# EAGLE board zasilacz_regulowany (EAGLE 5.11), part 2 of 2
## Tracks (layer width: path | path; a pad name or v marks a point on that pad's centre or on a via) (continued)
N$5 (continued)
  Top 0.406: 17.59,198.58 R34.2 | 17.59,198.58 17.77,198.51 IC6.7 | IC6.10 20.31,197.5 17.77,197.5 17.77,198.13 17.84,198.57 17.59,198.58
N$6  (via drill 0.6 pad 1.42)
  Top 0.406: 25.52,191.27 25.14,191.65 C23.1 25.18,192 24.54,192 24.12,192.42 | 24.12,192.42 IC6.13 | 24.12,192.42 v23.36,191.65
  Bottom 0.406: CA6V1.S 29.97,202.7 30.73,201.94 30.73,199.27 29.97,198.51 29.97,196.73 30.47,196.23 30.47,193.56 29.33,192.42 24.12,192.42 v23.36,191.65
N$7
  Top 0.406: R45.1 15.3,197.18 15.62,196.86 15.62,196.61 15.87,196.35 15.93,196.41 R41.2 16.06,196.41 16.5,196.86 16.5,196.73 19.04,196.73 IC6.9 19.04,192.54 19.93,191.65 20.02,191.74 C19.2
N$8  (via drill 0.6 pad 1.42)
  Top 0.406: R41.1 17.58,194.51 17.77,194.32 IC6.8 17.77,192.8 | 17.77,192.8 17.77,191.53 19.17,190.13 19.55,190.13 19.68,190 19.72,190.04 C19.1 | 17.77,192.8 v16.38,192.8 | CA6V1.E 27.43,206.01 27.36,206.07 R73.1
  Bottom 0.406: v16.38,192.8 19.93,196.35 19.93,200.8 21.33,202.2 22.35,202.2 22.98,202.83 22.98,205.37 23.24,205.62 27.17,205.62 CA6V1.E
N$9
  Top 0.406: LED10_V.K 66.92,61.5 68.7,63.28 77.21,63.28 78.1,62.39 78.1,58.58 79.24,57.44 81.91,57.44 82.04,57.57 R24.1
N$10  (via drill 0.6 pad 1.27)
  Top 0.406: Q3.3 36.27,185.77 36.19,185.69 35.94,185.94 v35.94,187.59 | 3.3,182.76 8.88,182.76 11.3,185.18 13.58,185.18 14.73,186.32 17.62,186.32 v18.18,186.88 | C18.1 32.89,190.38 34.21,189.07 D13.A
  Top 0.61: D13.A 34.28,188.1 33.45,187.26 D12.A 33.45,185.51 33.52,185.43 33.86,185.77 Q3.3 37.67,185.77 38.48,186.57 | 38.48,186.57 T5.3 | C1.1 39.87,185.18 38.48,186.57 | 3.3,182.76 1.65,184.42 1.65,196.48 3.8,198.64 3.8,233.21 4.11,233.51 Q2.B
  Bottom 0.406: v18.18,186.88 18.89,187.59 v35.94,187.59
N$11
  Bottom 0.406: TRAN2.1 53.39,182.94 53.08,182.64 R120.2
N$12  (via drill 0.6 pad 1.27)
  Top 0.305: IC5.32 50.42,200.41 v51.43,199.4
  Bottom 0.406: v51.43,199.4 51.43,193.05 53.46,193.05 56.64,189.88 56.64,188.61 57.02,188.23 57.02,186.32 56,185.3 56,183.27 55.98,183.37 TRAN2.2
N$13
  Bottom 0.305: TP1.PP 14.73,116.27 16.76,114.23 16.76,110.68 18.54,108.9 21.58,108.9 21.84,109.15 22.98,109.15 23.03,109.1 IC9.30
N$14
  Top 0.406: CA6V.E 29.08,193.81 29.71,193.18 30.6,193.18 31.05,192.73 R70.2
N$15
  Bottom 0.305: TP2.PP 16.38,115.89 17.39,114.87 17.39,111.06 18.92,109.54 21.33,109.54 21.71,109.92 23.11,109.92 23.24,109.79 23.35,109.9 IC9.31
N$16
  Top 0.406: IC6.14 25.39,194.19 26.66,192.92 26.66,191.78 26.79,191.65 C23.2 27.68,191.65 28.95,190.38 28.95,186.7 30.04,185.61 D12.C 30.04,185.51 29.59,185.05 29.59,178.7 30.98,177.3 R63.2
N$17
  Top 0.406: R66.1 26.1,209.63 CA6V1.A
N$18
  Bottom 0.305: TP3.PP 18.03,112.96 18.16,112.84 18.16,111.19 19.17,110.17 21.08,110.17 21.58,110.68 23.11,110.68 23.13,110.7 IC9.32
N$19
  Top 0.406: R32.2 15.62,204.61 13.33,206.87 13.33,210.7 9.52,214.51 9.52,223.91 10.15,224.55 10.15,224.42
  Top 0.61: 6.85,226.71 6.85,226.58 6.73,226.45
  Top 2.184: R29.1 6.85,226.71 7.36,226.71 9.65,224.42 10.15,224.42 14.09,224.42 18.41,228.74 24.78,228.74 25.75,229.7 25.75,232.95 Q4.E
N$20
  Top 0.406: LED9_I.K 79.37,60.62 80.39,59.6 82.16,59.6 | 82.16,59.6 82.1,59.66 R25.1 | 82.16,59.6 82.29,59.47
N$21
  Bottom 0.406: 38.98,77.02 39.11,76.9 J2.4 38.98,78.55 40,79.56 D11.C
N$22
  Top 0.406: R27.2 41.52,185.18 41.78,184.92 R14.1 41.72,183.33 42.41,182.64 D4.A
N$23
  Top 0.406: D1.C 36.65,178.65 38.78,180.78 D2.A
N$24
  Top 0.406: Q18.3 74.16,32.04 75.43,33.31 75.43,40.3 80.26,45.12 80.26,53.88 76.83,57.31 LED9_I.A
N$25
  Top 0.406: R33.2 39.55,189.05 39.43,188.92 T5.1 39.58,188.82 39.68,188.92 R27.1
N$26
  Bottom 0.305: TP4.PP 19.68,113.35 18.79,112.46 18.79,111.44 19.43,110.81 20.7,110.81 21.46,111.57 23.11,111.57 23.24,111.44 23.3,111.5 IC9.33
N$27
  Bottom 0.305: TP5.PP 21.33,116.27 23.24,114.36 24.63,114.36 25.14,113.85 25.14,113.35 25.18,113.3 IC9.34
N$28
  Bottom 1.27: Q4.B 14.83,232.9 14.17,233.56 Q2.E
N$29
  Bottom 0.305: TP6.PP 24.25,115.12 25.14,115.12 26.03,114.23 26.03,113.47 25.9,113.35 25.94,113.3 IC9.35
N$30
  Bottom 0.305: TP7.PP 24.63,116.52 26.79,114.36 26.79,113.47 26.8,113.46 IC9.36
N$31  (1 unrouted)
N$32
  Bottom 0.305: TP8.PP 26.16,116.27 27.55,114.87 27.55,113.6 27.6,113.55 IC9.37
N$33  (via drill 0.6 pad 1.42)
  Top 0.406: 23.74,180.86 23.79,180.9 Q8.3 22.35,180.99 21.84,181.49 21.84,181.62 | Q7.3 22.22,186.7 21.84,186.32 21.84,181.62 | v21.2,181.62 21.84,181.62
  Bottom 0.406: v21.2,181.62 20.95,181.62 20.52,181.19 20.52,179.87 C52.+
N$34
  Top 0.406: R37.2 47.81,176.99 48.76,177.94 49.52,177.94 49.52,178.45 | 49.52,178.45 49.52,178.57 49.55,178.55 TRAN1.4 49.55,178.67 49.52,178.7 | IC4.4 52.19,183.53 49.52,180.86 49.52,178.7 | 49.52,178.45 49.52,178.7
N$35
  Top 0.305: 54.55,210.32 52.32,210.32 52.06,210.58 49.78,210.58 49.65,210.45 49.65,209.43 IC5.10 | 54.55,210.32 J9.2 | R35.1 54.61,210.38 54.55,210.32
N$36
  Top 0.406: D2.C 35.38,180.91 35.3,180.99 35.37,181.05 Q3.1 35.37,183.34 35.11,183.08 R22.1
N$37  (2 unrouted)
  Top 0.406: R63.1 31.04,175.46 31.49,175.02 | J10.6 31.49,172.22
  Top 0.61: 31.49,172.22 31.49,175.02
N$38  (2 unrouted)
  Top 0.61: R64.1 33.4,172.99 J10.5
N$39  (via drill 0.6 pad 1.27)  (1 unrouted)
  Top 0.305: v40.25,203.72 41.14,203.72 41.78,203.08 43.3,203.08
  Top 0.406: R2.1 17.71,213.82 18.41,213.12 21.71,213.12 21.97,213.37 R3.2 22.03,211.91 v22.47,211.47 | 43.3,203.08 IC5.23
  Route2 0.254: 43.68,200.7 46.48,205.78
  Bottom 0.406: v22.47,211.47 25.01,214.01 33.65,214.01 35.94,211.72 35.94,207.4 39.62,203.72 v40.25,203.72
N$40
  Top 0.406: R2.2 15.87,215.91 13.84,217.94 D3.A | R39.2 20.06,205.75 19.49,206.33 R36.1 18.35,206.33 18.41,206.39 18.41,210.7 17.65,211.47 C46.+ | D5.A 6.47,190.64 7.91,192.07 C49.2
  Bottom 1.016: 6.6,211.59 C46.+
  Bottom 1.778: 6.6,195.08 6.6,211.59 6.6,214.51 10.03,217.94 D3.A
  Bottom 1.93: 6.6,195.08 R29.2 D5.A
N$41
  Top 2.54: 7.74,164.73 7.74,169.81
N$42  (via drill 0.6 pad 1.42)
  Top 0.406: v22.22,178.95 23.36,178.95 24.25,178.07 D14.C 24.81,178.37 25.01,178.57 26.54,178.57 26.79,178.32 D15.A
  Bottom 0.406: v22.22,178.95 22.24,178.95 20.59,177.3 C52.-
N$43
  Top 0.406: R18.1 34.73,212.93 35.55,213.75 L2.2
N$44
  Top 0.406: 49.55,185.56 TRAN1.1 | 49.55,185.56 49.55,185.79 49.4,185.94 | R53.2 44.83,187.34 45.59,186.57 48.51,186.57 49.52,185.56 49.55,185.56
N$45
  Top 0.406: IC4.1 56,182.51 56.64,181.88 59.94,181.88 60.95,180.86 60.95,178.95 60.93,178.93 TRAN3.2
N$46
  Top 0.61: J4.7 76.7,28.74 81.28,24.17 81.28,15.15 78.86,12.74 72.13,12.74 70.48,11.09 70.48,8.93 70.45,8.95 LED12_POWER.A
N$47  (1 unrouted)
N$48
  Top 2.54: 12.69,164.86 12.69,169.94
N$49
  Top 2.54: 17.52,164.86 17.52,169.94
N$50
  Top 2.54: 22.47,164.86 22.47,169.94
N$51
  Top 2.54: 53.84,219.34 58.92,219.34
N$52
  Top 2.54: 53.84,224.42 58.92,224.42
N$53
  Top 0.406: Q18.1 71.18,32.99 74.16,35.98 J4.6
N$54
  Top 0.406: R38.2 58.54,176.41 58.39,176.57 TRAN3.1
N$55
  Bottom 0.406: R121.2 53.44,177.05 TRAN2.4 53.44,177.91 53.46,177.94 53.46,179.34 53.55,179.42 T2.1
N$56
  Top 1.016: IC3.OUT 36.6,230.95 38.5,229.04 L1.2
  Bottom 0.406: C8.1 39.64,226.22 L1.2
N$57  (1 unrouted)
  Top 0.406: R5.2 54.16,197.56 53.84,197.12 53.84,195.08 55.11,193.81 LED1.A
  Bottom 0.406: LED1.A 56.89,193.05 57.14,192.8 60.07,192.8 60.7,192.16 60.7,187.59 60.32,187.21 60.32,184.42 57.65,181.75 51.68,181.75 50.92,180.99 46.73,180.99 45.72,179.97 45.72,169.94 29.08,169.94 J10.7
N$58
  Bottom 0.406: C47.1 19.79,107.61 20.19,108.01 21.97,108.01 22.22,108.27 23.24,108.27 23.27,108.3 IC9.29
N$59  (via drill 0.6 pad 1.27)
  Top 0.406: v7.74,219.72 5.84,217.82 5.84,198 4.31,196.48 4.31,187.97 5.58,186.7 8.88,186.7 9.77,187.59 R119.2 | v21.84,219.47 21.84,219.21 22.47,218.58 24.25,218.58 | 24.25,218.58 24.19,218.64 R74.2 | 24.25,218.58 24.38,218.45
  Bottom 0.254: D7.C 10.66,174.13 10.98,174.45
  Bottom 0.406: v7.74,219.72 8.88,220.86 21.2,220.86 21.84,220.23 v21.84,219.47
  Bottom 0.61: 10.03,175.27 10.03,175.02 9.77,175.27
  Bottom 0.813: 10.03,175.02 9.77,174.76 R119.2
  Bottom 2.54: D5.C 10.03,175.27 10.15,175.27 10.98,174.45 12.69,172.73 12.69,169.81 | 12.69,169.81 12.75,169.86 X2.4 | X2.3 12.75,164.65 12.69,164.6 12.69,169.81
N$60  (via drill 0.6 pad 1.27)
  Top 0.406: IC6.1 25.39,200.8 25.65,201.05 27.05,201.05 27.17,201.18 27.08,201.27 C42.1 26.83,201.27 26.54,201.56 v26.54,202.83 | R64.2 33.34,177.36 32,178.7 31.24,178.7 30.6,179.34 30.6,183.65 31.49,184.54 31.49,187.21 30.81,187.89 D13.C 30.81,188.27 29.84,189.24 29.84,191.02 28.7,192.16 28.7,192.29 27.55,193.43 27.55,195.34 v27.17,195.72
  Bottom 0.406: v27.17,195.72 27.17,202.07 v26.54,202.83
N$61  (via drill 3.2)  (1 unrouted)
  other vias: 61.59,165.11 2.79,165.11
N$62  (via drill 0.6 pad 2.18)
  other vias: 91.03,90.59
N$63
  Top 0.406: R28.1 10.79,69.25 11.81,70.27 11.81,77.28 BPT-14X.2
  Bottom 0.406: BPT-14X.2 10.15,90.46 11.42,91.73 T8.3
N$64
  Top 0.406: R72.2 49.78,189.88 49.91,189.75 50.03,189.75 50.29,190 LRED.A
N$65  (via drill 0.6 pad 1.42)
  Top 0.406: IC4.2 IC4.3 | IC4.2 54.73,184.8 | IC4.2 54.73,182.13 56,180.86 58.8,180.86 59.94,179.72 59.94,177.3 v60.57,176.67
  Bottom 0.406: v60.57,176.67 60.53,176.67 | R6.2 50.67,179.34 52.06,180.73 60.32,180.73 60.95,180.1 60.95,177.05 v60.57,176.67 | v60.57,176.67 60.57,176.8 60.15,177.22 T2.3
N$66
  Top 0.406: 50.67,187.84 LGREEN.A R71.2
N$67  (via drill 0.6 pad 1.27)
  Top 0.406: Q3.2 37.27,182.2 v37.08,182 | v17.52,189.62 16.25,189.62 v14.09,191.78
  Bottom 0.406: v37.08,182 37.08,188.73 36.44,189.37 29,189.37 28.24,188.61 26.72,188.61 25.95,189.37 17.77,189.37 v17.52,189.62 | v14.09,191.78 11.55,191.78 8.38,194.7 8.38,197.5 9.14,198.26 10.03,198.26 12.95,201.18 R10.1
N$68  (via drill 0.6 pad 1.27)
  Top 0.406: 53.89,224.32 X1.4 53.23,224.98 v47.49,224.98
  Bottom 0.406: C11.2 57.69,228.95 57.4,229.25 55.82,229.25 55.77,229.2 55.06,229.2 55.01,229.25 54.96,229.25 | C12.1 46.54,225.93 v47.49,224.98
  Bottom 2.184: X1.4 53.92,224.34 53.97,224.29 54.02,224.34 54.96,224.34 X1.3
  Bottom 2.54: 54.96,224.34 54.96,229.25 B1.~2
N$69
  Bottom 0.254: 57.18,219.76 57.65,219.85 X1.1
  Bottom 0.406: C6.1 57.18,219.76 56.76,219.34 | C5.1 46.56,230.22 46.98,230.64 48.79,230.64 48.91,230.52 49.02,230.52
  Bottom 2.184: X1.2 53.97,219.34 | X1.2 51.3,219.34 50.16,220.48 50.16,226.33 49.02,227.47 49.02,230.52 49.02,232.14 49.93,233.06 B1.~1 | X1.2 X1.1 60.19,219.34
N$70
  Top 0.406: LED11_OFF_ON.K 70.48,57.31 71.88,55.92 75.31,55.92 78.35,52.87 78.35,45.88 75.18,42.71 67.81,42.71 66.54,41.44 J4.3
N$71
  Top 0.406: LED11_OFF_ON.A 73.02,57.31 73.53,56.81 75.69,56.81 79.24,53.25 79.24,45.5 75.56,41.82 70.61,41.82 69.08,40.3 J4.4 69.08,37.63
N$72
  Top 0.406: Q15.3 91.1,35.98 90.8,35.98 90.8,40.55 90.42,40.93 90.42,54.27 92.32,56.17 LED10_V1.A
N$73
  Top 0.406: LED10_V1.K 94.86,62.39 95.75,63.28 107.82,63.28 108.83,62.27 108.83,59.35 109.28,58.9 | 109.34,58.84 109.28,58.9 | 109.28,58.9 R21.1
N$74
  Top 0.406: R23.1 108.96,56.55 107.06,58.46 LED9_I1.K
N$75
  Top 0.61: J3.7 102.23,31.28 100.96,30.01 92.45,30.01 88.13,25.69 88.13,15.15 91.69,11.59 97.4,11.59 98.42,10.58 LED12_POWER1.A
N$76
  Top 0.406: LED9_I1.A 104.52,59.47 100.71,55.66 96.01,55.66 93.09,52.74 93.09,43.72 96.26,40.55 99.94,40.55 100.96,39.53 100.96,33.69 99.94,32.68 Q16.3
N$77
  Top 0.406: LED11_OFF_ON1.K 98.42,58.2 97.4,57.19 95.12,57.19 91.31,53.38 91.31,41.44 92.2,40.55 92.2,37.76 92.09,37.65 J3.3
N$78
  Top 0.406: LED11_OFF_ON1.A 100.96,57.82 99.56,56.42 95.63,56.42 92.2,53 92.2,42.71 94.74,40.17 94.74,37.76 94.63,37.65 J3.4
N$79
  Top 0.305: 25.59,123.44 26.92,122.36 26.92,120.71 26.54,120.33 26.54,118.81 27.68,117.66
  Top 0.406: U$7.RS 29.71,119.7 28.06,118.04 28.06,117.92 27.74,117.6 R98.1 27.68,117.66 | 25.59,123.44 R103.1
N$80
  Bottom 0.406: IC9.7 40.85,106.7 42.54,108.39 Q5.2 43.03,108.88 C35.2
N$81
  Top 0.406: LED10_V2.A 6.47,58.84 10.15,55.15 17.27,55.15 19.81,52.61 19.81,47.03 16.25,43.47 13.2,43.47 10.03,40.3 10.03,32.93 11.42,31.53 12.57,31.53 12.61,31.49 | 12.69,31.41 12.61,31.49 | 12.61,31.49 Q13.3
N$82
  Top 0.406: LED10_V2.K 9.01,62.39 9.65,63.03 18.79,63.03 19.93,61.89 19.93,58.96 21.71,57.19 R19.1
N$83
  Top 0.406: LED9_I2.K 21.2,60.62 22.09,59.73 R20.1 25.01,59.73
N$84
  Top 0.61: J6.7 24,33.95 24.38,33.56 24.38,14.51 22.22,12.36 14.47,12.36 12.57,10.45 LED12_POWER2.A
N$85
  Bottom 0.406: IC9.8 41.09,105.9 41.65,105.34 Q5.1 43.3,103.57 42.54,102.8 42.54,99.88 43.05,99.5 42.91,99.36 C36.2
N$86
  Bottom 0.406: R116.2 30.16,88.27 29.71,87.82 LED7.A
N$87
  Bottom 0.406: R117.2 27.93,88.2 27.81,88.07 27.81,86.55 27.55,86.29 LED8.A
N$88  (via drill 0.6 pad 2.18)
  other vias: 96.16,90.59
N$89
  Bottom 0.406: U$11.A 73.66,69.53 73.78,69.66 R84.2
N$90
  Top 0.406: R100.1 32,117.66 32.76,118.43 U$7.CS 32.76,128.33 31.74,129.35 27.93,129.35 24.89,126.3 23.36,126.3 20.7,123.63 20.82,123.51 R105.1
N$91
  Top 0.406: R101.1 33.97,117.6 33.78,117.79 33.78,118.3 34.28,118.81 U$7.CLK 34.28,128.59 32.63,130.24 27.55,130.24 24.51,127.19 22.22,127.19 18.66,123.63 R106.1
N$92
  Bottom 0.406: R86.2 103.37,69.78 103.25,69.91 101.72,69.91 100.96,69.15 U$13.A
N$93  (via drill 0.6 pad 1.42)
  Top 0.406: U$7.LED+ 41.91,122.24 42.41,121.73 42.41,119.95 v42.03,119.44
  Bottom 0.406: R109.2 48.45,120.65 48.51,120.58 47.37,119.44 v42.03,119.44
N$94
  Bottom 0.305: R90.1 37.84,127.51 37.84,130.87 44.7,130.87 45.97,129.6 45.97,127.95 46.48,127.44 U$8.7
  Bottom 0.406: R91.2 39.49,124.46 R90.1
N$95  (via drill 0.7 pad 1.42)
  Top 0.61: v56.26,121.85 55.88,121.35 55.88,82.36 55.37,81.85 55.37,77.4 56.26,76.52 L3.2
  Top 0.813: IC7.3 66.42,77.15 65.78,76.52 L3.2
  Bottom 0.61: C32.1 55.88,121.86 v56.26,121.85
N$96
  Bottom 0.406: LED6.A 59.05,89.47
  Bottom 0.61: 59.05,89.47 R81.2
N$97
  Top 0.406: 100.2,94.78 100.2,94.68 100.32,94.55 | B2.AC2 91.05,90.87 90.68,91.24 C30.2 | C29.2 105.28,84.9 108.45,88.07 108.45,93.91 107.56,94.8 105.53,94.8 105.51,94.78 U$6.1
  Top 0.813: B2.AC2 91.05,90.74 95.09,94.78 100.2,94.78 U$6.1 105.38,94.78 105.41,94.8
  Bottom 0.406: U$6.1 105.38,94.78
N$98  (via drill 0.6 pad 2.18)
  other vias: 91.08,85.53
N$99  (via drill 0.6 pad 2.18)
  other vias: 96.11,85.51
N$100  (1 unrouted)
  Top 0.305: R92.2 40.13,175.27 39.87,175.02
  Top 0.406: D4.C 42.49,179.03 | 39.87,175.02 39.24,174.38 J10.3 | 41.91,178.57 41.91,177.81 40.51,176.41 40.51,175.53 40.25,175.27 R92.2
  Top 0.61: D4.C 42.36,179.03 41.91,178.57
N$101
  Top 0.406: Q14.3 20.91,32.25 22.73,34.07 22.73,40.3 22.35,40.68 22.35,54.14 18.66,57.82 18.66,60.74 18.79,60.87 LED9_I2.A
N$102  (via drill 3.2)
  other vias: 114.09,200.65
N$103
  Top 0.406: J6.3 13.84,41.82 14.47,42.45 16.5,42.45 20.7,46.65 20.7,53 17.77,55.92 14.09,55.92 12.57,57.44 LED11_OFF_ON2.K
N$104
  Bottom 0.406: R87.2 U$14.A
N$105
  Bottom 0.406: Q6.3 53.08,113.47 53.21,113.6 D8.A 53.21,116.27 55.62,118.68 L4.2
N$106
  Bottom 0.406: D10.C 49.64,114.6 D9.A
N$107
  Bottom 0.406: D8.K 53.21,121.09 53.02,120.33 R109.1 50.35,120.65 50.41,120.58 50.41,119.19 49.25,118.03 D9.C
N$108
  Bottom 0.406: L4.1 57.4,105.98 56.64,105.22 R108.2
N$109
  Top 0.406: 96.01,85.66 B2.AC1 94.1,83.5 C26.1 | 96.13,86.88 96.06,86.88 95.6,87.34 90.37,87.34 88.84,85.81 C27.1
  Top 0.813: B2.AC1 96.13,86.88 96.13,87.06 98.85,89.77 105.23,89.77 105.28,89.72 U$6.2
N$110
  Top 0.406: C29.1 99.43,85.02 99.18,84.77 98.93,84.77 94.23,80.07 C26.2
  Top 0.61: C26.2 90.8,80.2 90.61,80.39
  Top 0.813: IC7.1 74.29,77.28 79.37,72.2 C33.+ 83.56,72.2 83.94,72.58 83.94,78.42 84.96,79.44 89.66,79.44 90.61,80.39 91.18,80.96 91.18,85.41 B2.+
N$111
  Top 0.406: R99.1 30.03,117.6 30.22,117.41 30.22,118.81 31.24,119.82 U$7.RESET 31.24,127.95 30.73,128.46 28.44,128.46 25.27,125.28 24.63,125.28 22.98,123.63 R104.1
N$112
  Bottom 0.813: Q1.D 25.01,222.39 24.76,222.13 J1.2
N$113
  Top 0.406: R102.1 36.32,117.66 35.81,118.17 U$7.DAT 35.81,128.71 33.4,131.13 26.92,131.13 23.87,128.08 21.2,128.08 16.57,123.44 R107.1
N$114
  Top 0.406: LED11_OFF_ON2.A 15.11,57.57 15.87,56.81 18.28,56.81 21.58,53.5 21.58,46.39 16.38,41.18 J6.4
N$115  (via drill 0.6 pad 1.27)
  Top 0.305: v30.47,218.45 34.16,218.45 37.08,215.53 37.08,213.63 37.46,213.24 39.36,213.24 40.51,214.39 47.24,214.39 48.76,212.86 48.76,209.56
  Top 0.406: 48.76,209.56 48.82,209.5 IC5.11
  Bottom 0.406: Q1.G 26.54,223.66 27.3,222.9 27.3,222.13 29.52,219.91 | 29.52,219.91 29.59,219.85 | 29.52,219.91 R7.1 29.65,219.27 v30.47,218.45
N$116
  Top 0.406: LED9_I3.K 50.54,59.73 R17.1
N$117
  Top 0.406: LED9_I3.A 46.73,57.19 50.29,53.63 50.29,39.91 50.8,39.41 50.8,33.31 49.52,32.04 Q12.3
N$118
  Top 0.406: Q12.1 47.17,32.99 49.52,35.34 J8.6
N$119
  Top 0.61: J8.7 52.06,15.53 49.65,13.12 43.3,13.12 40.63,10.45 LED12_POWER3.A
N$120
  Bottom 0.406: U$15.A 43.68,69.4 43.94,69.66 R88.2
N$121
  Top 0.406: J8.5 46.98,36.1 45.21,34.33 45.21,32.29 43.94,31.02 43.43,31.02 43.36,31.09 Q11.1
N$122
  Top 0.406: J8.3 41.91,42.07 42.41,42.58 44.95,42.58 48.51,46.14 48.51,52.61 45.33,55.79 42.67,55.79 40.63,57.82 LED11_OFF_ON3.K
N$123
  Top 0.406: LED11_OFF_ON3.A 43.17,57.19 43.68,56.68 45.97,56.68 49.4,53.25 49.4,45.76 44.44,40.8 J8.4
N$124  (1 unrouted)
N$125
  Top 0.406: R30.1 8.63,69.78 BPT-14X.1
  Bottom 0.406: BPT-14X.1 10.15,75.86 8,78.01 8,91.98 8.38,92.37 8.38,92.9 Q19.2
N$126  (1 unrouted)
N$127  (via drill 3.2 pad 4)  (1 unrouted)
  Top 0.254: v110.74,3.74 111.75,5.01 111.75,7.55 v110.74,9.08
  other vias: 110.99,130.24
N$128  (1 unrouted)
N$129
  Top 0.406: J8.2 39.36,35.34 41.4,33.31 42.92,33.31 43.17,33.06 | 43.26,32.97 43.43,32.8 | 43.26,32.97 Q11.2 43.24,32.99 43.17,33.06 | 43.26,32.97 43.17,33.06 | Q12.2 47.16,30.43 46.48,29.75 42.92,29.75 42.16,30.52 42.16,32.04 43.17,33.06
N$130  (1 unrouted)
N$131
  Top 0.406: LED10_V3.A 34.54,59.47 39.11,54.9 44.7,54.9 47.49,52.11 47.49,46.52 44.44,43.47 41.65,43.47 38.09,39.91 38.09,33.56 39.62,32.04 Q11.3 | Q11.3 41.14,32.04 | Q11.3 41.4,32.04
N$132
  Top 0.406: LED10_V3.K 37.08,61.25 38.6,62.77 47.24,62.77 48,62.01 48,58.46 49.02,57.44 R16.1
N$133
  Top 0.406: Q14.1 18.71,32.25 18.66,32.29 21.46,35.09 J6.6
N$134
  Top 0.406: J6.5 18.92,35.6 16.5,33.18 16.5,32.29 14.81,30.6 Q13.1
N$135
  Top 0.406: J6.2 11.3,35.85 14.73,32.42 14.79,32.48 Q13.2 14.81,32.46 14.85,32.42 13.71,31.28 13.71,28.87 17.77,28.87 18.71,29.8 Q14.2
N$136
  Top 0.406: Q16.1 97.6,33.63 97.66,33.56 99.69,35.6 J3.6
N$137
  Top 0.406: Q15.1 94.68,32.23 95.88,33.44 95.88,34.71 97.15,35.98 J3.5
N$138
  Top 0.406: Q16.2 97.47,31.73 97.4,31.79 96.77,31.15 92.32,31.15 | 92.32,31.15 92.2,31.15 92.2,33.18 93.15,34.13 Q15.2 | J3.2 89.53,31.15 92.32,31.15
N$139
  Top 0.406: J4.5 71.62,36.74 68.96,34.07 68.96,33.31 66.88,31.24 Q17.1
N$140
  Top 0.406: J4.2 64,35.85 66.8,33.06 66.86,33.12 Q17.2 66.88,33.14 | Q18.2 71.16,29.37 65.78,29.37 65.78,31.91 66.88,33.14 | 66.92,33.18 66.88,33.14
N$141
  Top 0.406: LED10_V.A 64.44,60.95 70.35,55.03 74.42,55.03 77.34,52.11 77.34,46.39 74.67,43.72 64.89,43.72 62.73,41.57 62.73,32.29 62.86,32.17 Q17.3 64.89,32.17
N$142  (via drill 0.6 pad 1.27)  (1 unrouted)
  Top 0.305: U$16.6 35.55,207.91 35.55,204.1 36.06,203.59 36.06,201.56 35.81,201.31 35.81,197.5 36.32,196.99 38.35,196.99 | v43.56,200.42 44.57,200.42 | IC5.20 46.24,205.52 v46.6,205.88
  Top 0.406: U$9.6 38.22,196.99 38.35,196.99 42.03,196.99 42.92,197.88 R11.1 43.11,195.53 VR1.C VR1.R | 48.64,194.07 48.38,194.07 | 44.57,200.42 44.83,200.54 44.83,200.8 44.82,200.8 IC5.25 | VR1.R 46.35,194.83 | 48.64,194.07 C2.1 | VR1.R 47.75,194.96 48.64,194.07
  Bottom 0.305: C15.2 46.86,207.53 46.6,207.28 v46.6,205.88
  Bottom 0.406: VR1.C 43.68,200.29 v43.56,200.42
N$144  (1 unrouted)
  Top 0.406: R9.1 44.7,174.64 45.84,173.49 45.84,169.81 45.08,169.05 37.59,169.05 36.7,169.94 J10.4
PIK  (via drill 0.7 pad 1.42)
  Top 0.406: v11.3,100.26 11.3,99.25 12.82,97.72 29.33,97.72 30.22,96.84 v30.22,94.42
  Bottom 0.406: IC9.16 30,99.59 30.22,99.38 v30.22,94.42 | 10.45,95.01 10.41,95.06 10.47,95.12 R118.2 | 10.45,95.01 T8.1 10.47,99.44 v11.3,100.26 | 10.45,95.01 8.51,95.01 Q19.1
PWM_LCD  (via drill 0.7 pad 1.42)
  Top 0.406: v32.89,97.72 31.49,99.12 31.49,104.71 32.51,105.73 40,105.73 40.63,105.09 40.63,97.72 v41.78,96.58
  Bottom 0.406: Q6.1 54.56,111.23 55.11,110.68 55.11,109.28 R111.1 52.63,109.09 52.7,109.03 51.56,107.88 49.91,107.88 48.25,106.23 48.25,99.38 45.46,96.58 v41.78,96.58 | IC9.14 31.6,99.01 v32.89,97.72
RESET_LCD  (via drill 0.6 pad 1.42)
  Top 0.406: R104.2 v22.98,119.82 R97.1
  Bottom 0.406: v22.98,119.82 24.25,121.09 32,121.09 33.4,119.7 33.4,115.5 32.38,114.49 32.38,113.6 32.41,113.57 IC9.43
RS_LCD  (via drill 0.6 pad 1.42)
  Top 0.406: R103.2 v25.27,119.95 R96.1
  Bottom 0.406: v25.27,119.95 26.66,118.55 31.62,118.55 31.62,116.01 30.86,115.25 30.86,113.47 30.8,113.42 IC9.41 30.86,113.25 30.86,113.22
RST  (via drill 0.6 pad 1.27)
  Top 0.305: IC5.29 48.02,202.09 48.38,202.45 50.29,202.45 v51.81,200.93
  Top 0.406: R8.1 56.26,196.35 56.89,195.72 56.89,194.45 57.27,194.07 SV2.5 58.92,194.07
  Bottom 0.406: v51.81,200.93 51.81,200.67 53.08,199.4 53.08,195.34 54.1,194.32 58.54,194.32 SV2.5
RST_G
  Bottom 0.406: IC9.4 36.39,109.1 38.73,111.44 38.73,115.5 | 40.89,115.5 41.02,115.5 41.08,115.44 R113.1 40.89,115.5 | 38.73,115.5 40.89,115.5 | 38.73,115.5 38.73,121.6 35.68,124.65 16.12,124.65 13.96,122.49 13.96,121.09 13.71,120.84 SV3.5
RXD  (via drill 0.6 pad 1.27)
  Top 0.305: IC5.30 48.76,200.77 48.76,199.27 v48.38,198.77
  Top 0.406: TRAN3.4 58.31,185.28 | 58.39,185.43 58.41,185.43 | TRAN3.4 58.39,185.43 | 58.39,185.43 58.29,185.43 | LGREEN.C 55.37,187.84 v55.88,187.34 | v55.88,187.34 55.98,187.23 57.63,187.23 58.41,186.45 58.41,185.56 58.39,185.53 TRAN3.4 | R54.2 55.49,187.84 v55.88,187.34
  Bottom 0.406: v48.38,198.77 48.38,198 49.52,196.86 49.52,184.67 52.06,184.67 52.06,187.34 v55.88,187.34
RXD_G  (via drill 0.7 pad 1.42)
  Top 0.406: v38.86,104.46 38.86,85.41 34.41,80.96 29.97,80.96 v29.71,80.71 27.55,78.55 J11.3
  Bottom 0.305: IC9.9 38.21,105.1 v38.86,104.46
  Bottom 0.406: LED7.C v29.71,80.71 30.22,81.21 IC10.1
SCK  (via drill 0.6 pad 1.27)
  Top 0.305: IC5.17 43.05,207.92 | v42.03,211.21 42.16,211.21 43.3,210.07 43.3,207.91 IC5.17 | 43.17,207.91 43.18,207.92 IC5.17
  Bottom 0.406: v42.03,211.21 41.91,211.21 41.91,214.77 59.56,214.77 60.7,213.63 60.7,207.53 58.8,205.62 SV2.1
SCK_DA
  Top 0.305: U$9.3 38.22,201.43 37.71,201.94 37.71,203.97 36.82,204.86 36.82,207.91 U$16.3 39.75,207.91 40.13,208.29 40.13,212.1 41.02,212.99 46.6,212.99 47.24,212.36 47.24,209.43
  Top 0.406: 47.24,209.43 IC5.13
SCK_G  (via drill 0.6 pad 1.42)
  Top 0.406: R94.1 v18.66,119.82 R106.2
  Bottom 0.406: IC9.3 36.18,109.9 37.84,111.57 37.84,120.84 35.05,123.76 17.14,123.76 14.98,121.6 14.98,119.57 | 14.98,119.57 14.98,119.06 15.74,118.43 17.27,118.43 v18.66,119.82 | SV3.1 10.15,110.68 9.39,111.44 9.39,118.43 10.54,119.57 14.98,119.57
SCL
  Bottom 0.305: IC9.19 27.6,100.06 26.03,98.49 23.62,98.49 22.35,97.22 IC8.6
  Bottom 0.406: R82.2 20.25,90.81 22.35,92.9 IC8.6
SDA
  Bottom 0.406: IC9.20 26.8,100.4 25.65,99.25 23.24,99.25 21.08,97.09 21.08,94.68 20.98,94.58 | 20.98,94.58 20.95,94.55 | 20.98,94.58 IC8.5 21.05,94.58 20.95,94.68 20.89,94.62 R83.2
SDI
  Top 0.305: U$16.4 36.19,209.18 36.19,204.48 36.95,203.72 U$9.4 | 39.24,209.18 39.24,212.1 40.76,213.63 46.86,213.63 48,212.48 48,209.56
  Top 0.406: U$16.4 39.24,209.18 | IC5.12 47.98,209.41 48,209.43 48,209.56
TXD  (via drill 0.6 pad 1.27)
  Top 0.305: IC5.31 49.62,199.31 v49.91,199.15
  Top 0.406: 53.59,190.13 53.49,190.03 LRED.C 53.46,190 53.33,190.13 53.21,190.13 53.08,190.26 v53.08,191.78 | TRAN1.2 47.01,183.25 47.24,183.02 50.03,183.02 50.8,183.78 v50.8,186.07
  Bottom 0.406: 49.78,199.4 v49.91,199.15 50.41,198.77 50.41,191.78 50.8,191.78 | 50.8,191.78 v53.08,191.78 | v50.8,186.07 50.8,191.78
TXD_G  (via drill 0.7 pad 1.42)
  Top 0.406: v37.71,103.19 37.71,86.42 33.78,82.48 27.93,82.48 27.3,81.85 v27.3,80.71 26.03,80.71 25.01,79.69 J11.2 24.89,76.77
  Bottom 0.406: IC9.10 37.23,104.3 37.59,103.95 37.59,103.31 v37.71,103.19 | v27.3,80.71 27.68,80.71 27.68,82.61 27.65,82.61 LED8.C 27.55,82.74 28.95,84.14 30.22,84.14 31.11,85.02 IC10.4
V+  (via drill 0.6 pad 1.27)
  Top 0.254: 40.25,178.83 39.87,178.7 D1.A
  Top 0.406: C1.2 39.96,182.93 40.38,182.51 40.38,178.95 40.25,178.83 40,178.57 40.05,178.52 | R4.1 19.75,217.24 19.3,217.69 17.01,217.69 16.5,218.2 16.5,220.23 14.92,221.82 | IC12.IN 13.46,183.91 16.91,180.45 v16.91,179.64 | D1.A 40.05,178.37 v36.57,174.89
  Top 0.813: R10.2 11.17,215.28 11.17,220.74 11.93,221.5 14.6,221.5 14.92,221.82 17.77,224.67 18.79,224.67 18.84,224.72 18.89,224.67 J1.1
  Bottom 0.406: IC12.IN 12.82,183.91 11.3,185.43 11.3,189.5 10.66,190.13 9.01,190.13 8.5,189.62 8.5,187.46 7.87,186.83 2.53,186.83 | 36.62,174.84 v36.57,174.89 35.4,176.06 18.89,176.06 16.91,178.04 v16.91,179.64 | B1.+ 44.8,233.01 44.5,232.7 44.5,230.67 44.86,230.3 C5.2 44.83,230.14 44.5,229.8 44.5,228.28 44.84,227.94 C12.2
  Bottom 0.61: 26.54,228.36 26.54,227.98 26.41,227.85
  Bottom 0.813: 8,230.01 8,229.75 7.87,229.88 | 2.53,205.5 3.17,205.5 | 18.89,228.36 18.89,228.08 18.92,228.05 18.92,224.7 18.89,224.67 | 18.89,224.67 18.84,224.62 | 18.89,224.67 J1.1
  Bottom 1.422: 6.65,230.01 Q2.C | C9.+ 46.86,220.89 42.01,225.74 42.01,233.06
  Bottom 1.676: 31.54,228.36 31.54,228.53 31.52,228.56 IC3.IN
  Bottom 1.778: 13.41,228.36 13.41,228.23 13.46,228.18 D3.C
  Bottom 2.54: 2.53,214.51 2.53,205.5 2.53,186.83 2.53,172.6 5.2,169.94 7.61,169.94 7.64,169.91 X2.2 X2.1 7.74,164.86 | 2.53,214.51 2.53,214.64 | 7.97,230.01 6.65,230.01 5.46,230.01 2.53,227.09 2.53,214.51 | 7.97,230.01 8,230.01 | 20.31,228.36 18.89,228.36 13.41,228.36 9.62,228.36 7.97,230.01 | 20.31,228.36 26.54,228.36 31.54,228.36 32.25,228.36 32.25,228.38 33.57,229.7 37.44,229.7 40.79,233.06 42.01,233.06 B1.+ | 20.31,228.36 Q4.C
V_WE  (via drill 0.6 pad 1.27)
  Top 0.305: v40.76,202.32 43.17,202.32
  Top 0.406: R4.2 21.27,215.34 21.71,215.78 21.84,215.66 R12.1 21.9,217.12 v22.09,217.31 | 43.17,202.32 43.18,202.32 IC5.24
  Bottom 0.406: v22.09,217.31 22.09,213.12 21.33,212.36 21.33,210.58 21.97,209.94 23.24,209.94 24,210.7 24,211.85 25.27,213.12 33.4,213.12 35.17,211.34 35.17,206.26 39.11,202.32 v40.76,202.32
VCC_RS485  (via drill 0.6 pad 1.27)
  Top 0.406: R37.1 49.71,175.72 v48.51,174.51 | IC4.8 56,177.05 56.64,176.41 R38.1 56.7,175.08 v56.13,174.51 57.27,174.51 J7.1 57.27,172.1 58.68,170.69 C13.2
  Bottom 0.406: 49.02,174.51 v48.51,174.51 48.51,174.64 48.58,174.64 R121.1 | 49.02,174.51 53.46,174.51 | 53.46,174.51 v56.13,174.51 | 49.02,174.51 48.96,174.57 | 53.46,174.51 53.44,174.51 | R121.1 R6.1 | R121.1 48.64,177.05
VOUT
  Top 0.406: U$16.8 30.09,205.37 29.33,204.61 29.33,204.23 28.95,203.85 26.92,203.85 26.79,203.97 25.52,203.97 25.14,203.59 25.14,202.58 24.76,202.45 | IC6.3 22.85,200.8 23.11,201.05 23.36,201.05 24.76,202.45 | 24.76,202.45 R69.2
ZAS_ON_OFF  (via drill 0.6 pad 1.27)
  Top 0.406: 42.09,174.83 R92.1 42.09,175.33 42.79,176.03 v42.79,176.92 | v53.46,203.34 53.21,203.08 52.06,203.08 52.03,203.12 IC5.2
  Bottom 0.406: v53.46,203.34 53.21,203.08 50.03,203.08 47.24,200.29 47.24,197.37 48.51,196.1 48.51,188.35 47.24,187.08 44.06,187.08 43.17,186.19 43.17,177.3 v42.79,176.92
(copper drawn outside any net)
  shapes: Top area x8

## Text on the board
Top: -
Bottom: - | - | - | + | + | + | +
